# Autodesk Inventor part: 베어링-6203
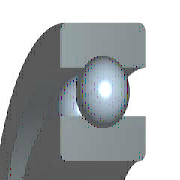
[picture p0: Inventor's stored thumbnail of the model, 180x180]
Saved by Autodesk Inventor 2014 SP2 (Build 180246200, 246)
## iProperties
IsCustomPart: 0
Created: 2016-05
Part Number: 베어링-6203
Material: 강철, 연강
Description: 깊은 그루브 볼 베어링
Document SubType Name: Modeling
Standard: KS B 2023
Designer: mduedu
Standards Organization: KS
Language: ko-KR
Size Designation: 6203 - 17 x 40 x 12
Categories: <MemberInstance><Categories><Category DisplayName="샤프트 부품" InternalName="7f7aeb1f-a693-4053-b835-cee3144e0d98" Mnemonic="SHFT"><Category DisplayName="베어링" Inter
Density: 1 g/cm^3
Appearance: 노란색
Author: mduedu
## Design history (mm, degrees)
sketch "스케치" dims "d0" = 5.98 (= -0.26 x WD + 0.26 x BD)
  geometry: L1 (3.01, 14.25)-(8.99, 14.25); L2 (6, 14.25)-(6, 11.26); L3 (6, 14.25)-(6, 17.24); L4 (3.778, 12.249)-(0, 12.249); L5 (0, 8.5)-(12, 8.5); L6 (3.778, 16.251)-(0, 16.251); L7 (0, 20)-(12, 20); L8 (12, 8.5)-(12, 12.249); L9 (8.222, 12.249)-(12, 12.249); L10 (8.222, 16.251)-(12, 16.251); L11 (12, 20)-(12, 16.251); L12 (-1.4, 0)-(8.4, 0) reference; L13 (0, -0.3)-(0, 5.3) reference
  constraints: 22 end point, 4 point on line, 2 collinear, 2 perpendicular, 2 symmetric about line, 1 midpoint, 1 parallel, 14 other
  dimensions: "d9" = 17 diameter of L5 L12 (= WD); "d11" = 40 diameter of L7 L12 (= BD); "d12" = 12 distance between parallel lines of L8 L13 (= KB); "d13" = 24.498 diameter of L9 L12 (= 0.326 x BD + 0.674 x WD)
revolve "본체" stored, may be unused: angle "d6" = 90 deg
revolve "볼" stored, may be unused: angle "d7" = 90 deg
pattern_circular "IDS_ARRAYBALL[SIMPL:T]" dims angle "d3" = 360 deg
body "Solid1"
fillet "모깎기1" dims "d1" = 0.6 (= KRS)
other parameters: "WD" = 17 [user parameter; used in 5 equation terms], "BD" = 40 [user parameter; used in 5 equation terms], "KB" = 12 [user parameter; used in 1 equation term], "KRS" = 0.6 [user parameter; used in 1 equation term], "d4" = 0, "d5" = 0, "d8" = 0, "d14" = 0, "d15" = 0, "BBA" = 0 [user parameter], "BC0" = 4750000 [user parameter], "BC" = 9560000 [user parameter], "WR" = 8.5 (= 0.5 x WD) [user parameter]
